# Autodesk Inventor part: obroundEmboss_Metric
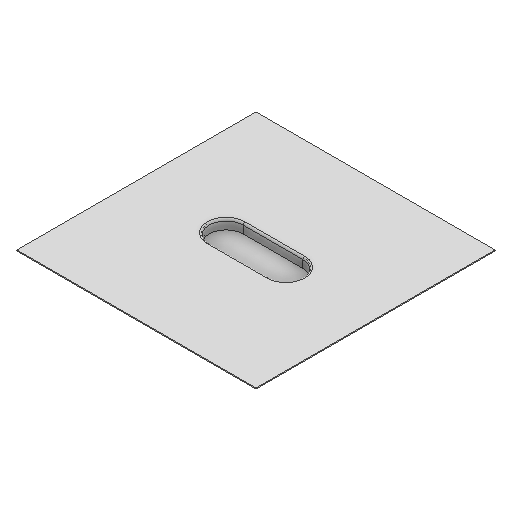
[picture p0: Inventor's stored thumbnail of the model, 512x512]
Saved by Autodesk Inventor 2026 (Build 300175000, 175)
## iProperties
Created: 2025-05
Part Number: obroundEmboss_Metric
Material: Generic
Document SubType Name: Sheet Metal
Designer: Autodesk, Inc
Density: 1 g/cm^3
Sheet Metal Rule: Default_mm
Appearance: Default
Author: Autodesk, Inc
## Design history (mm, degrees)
node "Face1"
  sketch "Sketch1"
    geometry: L1 (-63.5, 63.5)-(63.5, 63.5); L2 (63.5, 63.5)-(63.5, -63.5); L3 (63.5, -63.5)-(-63.5, -63.5); L4 (-63.5, -63.5)-(-63.5, 63.5); L5 (-63.5, 63.5)-(63.5, -63.5); L6 (63.5, 63.5)-(-63.5, -63.5); 1 further point
    constraints: 12 end point, 2 midpoint, 2 parallel, 2 perpendicular, 1 horizontal
    dimensions: "d0" = 127 distance of L1.end L2.end
sketch "Sketch2"
  geometry: L1 (-25.4, 0)-(25.4, 0); L2 (-15.875, -9.525)-(15.875, -9.525); L3 (15.875, 9.525)-(-15.875, 9.525); L4 (-24.9, 0)-(24.9, 0); L5 (-15.875, -9.025)-(15.875, -9.025); L6 (15.875, 9.025)-(-15.875, 9.025); A1 r 9.525 centre (-15.875, 0) between (-15.875, 9.525) and (-15.875, -9.525); A2 r 9.525 centre (15.875, 0) between (15.875, -9.525) and (15.875, 9.525); A3 r 9.025 centre (-15.875, 0) between (-15.875, 9.025) and (-15.875, -9.025); A4 r 9.025 centre (15.875, 0) between (15.875, -9.025) and (15.875, 9.025); 9 further points
  constraints: 16 end point, 16 point on circle, 8 tangent, 4 centre point, 4 point on line, 3 coincident, 3 parallel, 2 concentric, 2 midpoint, 1 horizontal
  dimensions: "length" = 50.8 distance of point (25.4, 0) point (-25.4, 0); "width" = 19.05 distance between parallel lines of L2 L3; "d12" = 49.8 distance of point (24.9, 0) point (-24.9, 0) (= length - 2 x Thickness)
extrude "Extrusion1" join sketch "Sketch2" distance "d5" = 5.58 (= Thickness + depth); taper "d6" = 0 deg
extrude "Extrusion2" cut sketch "Sketch2" distance "d7" = 5.08 (= depth); taper "d8" = 0 deg
fillet "Fillet1" dims "d9" = 1 (= fillet_radius)
body "Solid1"
face "Plate1" dims "d1" = 0.5 (= Thickness)
other parameters: "Thickness" = 0.5, "BendRadius" = 0.5 (= Thickness), "BendReliefWidth" = 0.5 (= Thickness), "BendReliefDepth" = 0.25 (= 0.5 x Thickness), "CornerReliefSize" = 2 (= 4 x Thickness), "SeamGap" = 0.01, "MinimumRemnant" = 1 (= 2 x Thickness), "TransitionRadius" = 0.5 (= BendRadius), "JacobiRadiusSize" = 0.5 (= BendRadius), "GapSize" = 0.5 (= Thickness), "fillet_radius" = 1 [user parameter; used in 1 equation term], "depth" = 5.08 [user parameter; used in 2 equation terms]
